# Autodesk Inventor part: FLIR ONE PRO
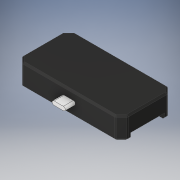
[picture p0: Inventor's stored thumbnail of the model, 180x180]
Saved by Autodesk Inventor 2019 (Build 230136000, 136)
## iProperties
Created: 2019-07
Part Number: FLIR ONE PRO
Material: ABS Plastic
Document SubType Name: Modeling
Designer: utente
Density: 1.06 g/cm^3
Appearance: Default
Title: C:/Users/lacon/Desktop/FLIR ONE PRO.step
Sending System: Autodesk Translation Framework v8.2.0.1029
Preprocessor: ST-DEVELOPER v18
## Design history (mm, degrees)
feature "Body1"
node "Solido1"
